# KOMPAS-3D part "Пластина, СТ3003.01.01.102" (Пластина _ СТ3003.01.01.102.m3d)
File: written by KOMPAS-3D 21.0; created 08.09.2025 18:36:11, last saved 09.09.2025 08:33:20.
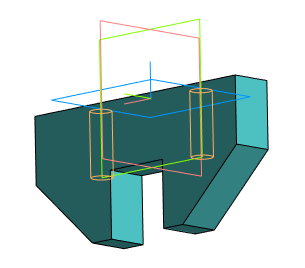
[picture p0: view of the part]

Document properties: Полное имя файла: C:\Users\1\Yandex.Disk\Документы\Новая папка\Стапель №2\Стапель _ СТ3003.00.00.000\Опора _ СТ3003.01.00.000\3D\Кронштейн _ СТ3003.01.01.000\Основание _ СТ3003.01.01.100\Пластина _ СТ3003.01.01.102.m3d

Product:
- Part/product: Пластина  | designation СТ3003.01.01.102
    Материал: Лист$dБ-ПН-НО-16 ГОСТ 19903-2015;Ст3сп ГОСТ 14637-89$ (density 7850 kg/m3)
    Масса: 0.442831
    Форматы листов документа: A4

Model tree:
1. Эскиз:1
2. Элемент выдавливания:1
     Расстояние 1 = 16
3. Эскиз:10  (with: Элемент выдавливания:1)
4. ЛСК:7  (with: Плоскость XY, Плоскость ZX, Плоскость ZY, Ось X, Ось Y, Ось Z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)
     Ось X. Z = 1; Ось Y. X = 1; Ось Z. Y = 1; Координата X = 25; Точка начала. Х = 25
5. Эскиз:11
6. Элемент вращения:3
     Угол 1 = 360
7. Смещенная плоскость:3  (with: Элемент выдавливания:1)
     Расстояние = 0.923418
8. Условное изображение резьбы:3  (with: Элемент вращения:3)  (labels: 8x1,25)
     Длина резьбы = 24.0766; Шаг резьбы = 1.25; Номинальный диаметр резьбы = 8
9. Подгонка:3
10. Отверстие М8x25-30/1,6x45°
11. Эскиз:13  (with: Элемент выдавливания:1)
12. ЛСК:9  (with: Плоскость XY, Плоскость ZX, Плоскость ZY, Ось X, Ось Y, Ось Z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)
     Ось X. Z = 1; Ось Y. X = 1; Ось Z. Y = 1; Координата X = -25; Точка начала. Х = -25
13. Эскиз:14
14. Элемент вращения:4
     Угол 1 = 360
15. Смещенная плоскость:4  (with: Элемент выдавливания:1)
     Расстояние = 0.923418
16. Условное изображение резьбы:4  (with: Элемент вращения:4)  (labels: 8x1,25)
     Длина резьбы = 24.0766; Шаг резьбы = 1.25; Номинальный диаметр резьбы = 8
17. Подгонка:4
18. Отверстие М8x25-30/1,6x45° (1)  (labels: Лист$dБ-ПН-НО-16 ГОСТ 19903-2015;Ст3сп ГОСТ 14637-89$)

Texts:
  KTE.LIST=LTWD36N5dmSErgwNQxupvb
  Edge1
  Edge2
  СТ3003.01.01.102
